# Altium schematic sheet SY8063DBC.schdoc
size 127 x 101 mm
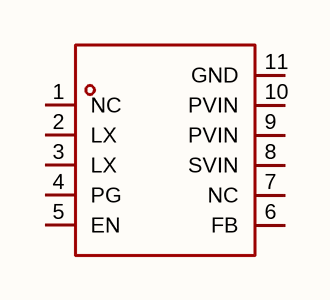
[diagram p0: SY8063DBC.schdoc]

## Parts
U?  sy8063dbc  [UDFN-10_L3.0-W3.0-P0.50-BL-EP]  (value not drawn)

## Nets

Not connected (* = marked no-connect by the designer): U? 1(NC) 2(LX) 3(LX) 4(PG) 5(EN) 6(FB) 7(NC) 8(SVIN) 9(PVIN) 10(PVIN) 11(GND)

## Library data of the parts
U? = sy8063dbc: 功能类型:降压型;工作电压:2.7V~5.5V;输出电压:-;输出电流:3.5A;输出类型:可调;; Manufacturer: Silergy(矽力杰); AddInBom: yes; ModelId: 807810ffc27348dabc433b239b2fd5d3; ModelTransform: 118.11,118.8974,0,0,0,0,0,0,0; Function: 降压型; Output Current: 3.5A; Frequency - Switching: 1MHz; Synchronous Rectifier: 是; Number of Outputs: 1; Topology: 降压式; Quiescent Current: 80uA; Switch tube (built-in/external): 内置; Output Type: 可调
